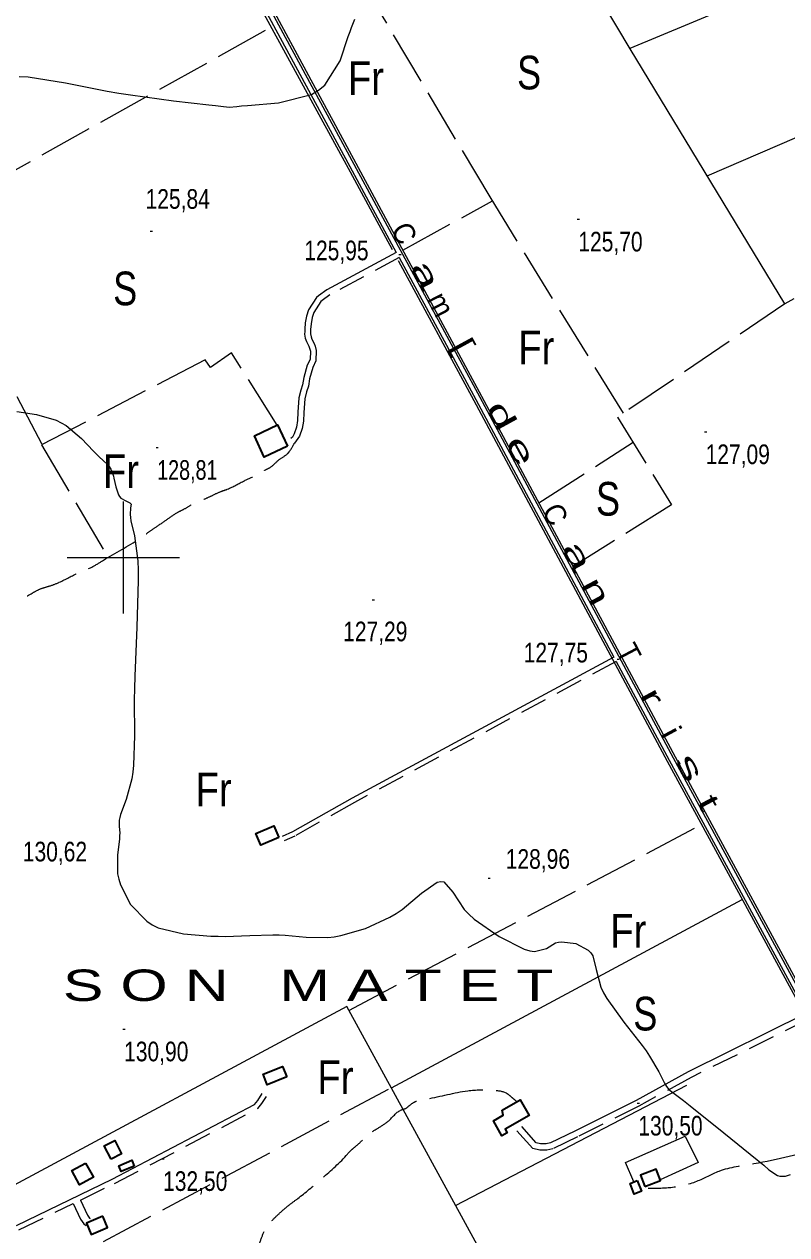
# Model space of a CAD drawing. Extents: x 487425 to 492029, y 4383576 to 4386788.
# Drawn here: x 488456 to 488796, y 4384698 to 4385238 of the extents above; entities that cross this region are included whole.
import ezdxf
from ezdxf.enums import TextEntityAlignment as Align

# ---------------------------------------------------------------- set-up
doc = ezdxf.new("R2010")
doc.units = 0
doc.header["$LTSCALE"] = 4
doc.linetypes.add('LONG_DASHED', pattern=[7.5, 6, -1.5])
doc.linetypes.add('MEDIUM_DASHED', pattern=[4.5, 3, -1.5])
for name, color, linetype, lineweight in [('1', 7, 'Continuous', 13), ('25', 7, 'LONG_DASHED', 25), ('38', 7, 'Continuous', 25), ('47', 7, 'Continuous', 35), ('51', 7, 'Continuous', 13), ('7', 7, 'Continuous', 13), ('8', 7, 'Continuous', 25), ('9', 7, 'Continuous', 13)]:
    doc.layers.add(name, color=color, linetype=linetype, lineweight=lineweight)
doc.layers.add('31', color=7, linetype='Continuous')
doc.layers.add('5', color=7, linetype='Continuous')

msp = doc.modelspace()

# ---------------------------------------------------------------- linework, layer by layer
at = {"layer": '1'}
for p, q in [((488500, 4385025), (488500, 4384975)), ((488475, 4385000), (488525, 4385000))]:
    msp.add_line(p, q, dxfattribs=at)
at = {"layer": '25'}
for p, q in [((488624.49, 4385136.87), (488664.45, 4385158.85)), ((488685.14, 4385024.33), (488727.05, 4385051.31)), ((488600.53, 4384798.28), (488757.61, 4384881.04)), ((488464.68, 4384681.15), (488619.38, 4384763.84))]:
    msp.add_line(p, q, dxfattribs=at)
for points in [[(488722.75, 4385064.26), (488663.36, 4385160.6), (488554.58, 4385343.42)], [(488463.94, 4385050.36), (488411.46, 4385150.11), (488566.15, 4385236.41)], [(488794.7, 4385112.97), (488720.16, 4385062.5), (488744.17, 4385023.44), (488700.34, 4384996)], [(488568.58, 4385058.95), (488548.16, 4385091.24), (488538.93, 4385084.59), (488536.42, 4385088), (488463.59, 4385050.19), (488492.89, 4385000.57)]]:
    msp.add_lwpolyline(points, dxfattribs=at)
at = {"layer": '38', "linetype": 'MEDIUM_DASHED'}
msp.add_line((488453.52, 4384700.52), (488477.75, 4384712.25), dxfattribs=at)
at = {"layer": '38'}
for points in [[(488512.49, 4385337.8), (488601.94, 4385172.22), (488621.59, 4385135.9)], [(488514.64, 4385338.17), (488603.76, 4385173.21), (488658.8, 4385071.45), (488744.97, 4384910.75), (488814.04, 4384783.4), (488837.88, 4384739.61)], [(488621.59, 4385135.9), (488590.67, 4385119.23), (488586.99, 4385116.53), (488586.05, 4385115.77), (488582.49, 4385110.29), (488581.66, 4385107.54), (488581.09, 4385104.47), (488580.83, 4385101.78), (488580.82, 4385100.7), (488580.8, 4385099.5), (488581.1, 4385097.73), (488581.58, 4385096.26), (488582.63, 4385094.19), (488583.03, 4385093.3), (488583.34, 4385091.89), (488583.23, 4385088.24), (488581.97, 4385085.64), (488580.45, 4385080.16), (488579.9, 4385076.96), (488579.05, 4385074.59), (488578.24, 4385071.12), (488577.78, 4385064.68), (488577.67, 4385060.96), (488577.2, 4385058.09), (488576.09, 4385055.13), (488575.33, 4385053.6), (488574.63, 4385053.04)], [(488622.83, 4385133.58), (488656.98, 4385070.46), (488718.58, 4384955.57)], [(488718.58, 4384955.57), (488601.92, 4384892.75), (488575.42, 4384877.82), (488570.83, 4384875.7)], [(488719.59, 4384953.71), (488743.15, 4384909.76), (488804.31, 4384796.99)], [(488804.31, 4384796.99), (488751.59, 4384770.9), (488728.41, 4384758.11), (488701.12, 4384744.55), (488690.36, 4384739.26), (488688.39, 4384738.87), (488685.81, 4384738.9), (488683.88, 4384739.3), (488677.49, 4384746.56)], [(488452.42, 4384702.52), (488495.02, 4384723.15), (488558.44, 4384756.33), (488559.88, 4384758.13), (488561.83, 4384761.19)], [(488480.92, 4384713.79), (488484.03, 4384707.09), (488484.93, 4384705.77), (488485.3, 4384705.55)]]:
    msp.add_lwpolyline(points, dxfattribs=at)
at = {"layer": '38', "linetype": 'MEDIUM_DASHED'}
for points in [[(488622.83, 4385133.58), (488592.08, 4385117.01), (488588.59, 4385114.45), (488588.02, 4385113.99), (488584.89, 4385109.18), (488584.22, 4385106.92), (488583.69, 4385104.1), (488583.46, 4385101.64), (488583.45, 4385100.66), (488583.43, 4385099.7), (488583.66, 4385098.36), (488584.01, 4385097.26), (488584.99, 4385095.32), (488585.53, 4385094.13), (488585.97, 4385092.14), (488585.83, 4385087.61), (488584.43, 4385084.71), (488583.01, 4385079.58), (488582.44, 4385076.29), (488581.57, 4385073.85), (488580.84, 4385070.73), (488580.4, 4385064.54), (488580.28, 4385060.71), (488579.75, 4385057.41), (488578.49, 4385054.08), (488576.26, 4385050.99)], [(488719.59, 4384953.71), (488602.94, 4384890.9), (488576.39, 4384875.94), (488571.71, 4384873.78)], [(488805.65, 4384794.52), (488752.89, 4384768.41), (488729.72, 4384755.62), (488702.37, 4384742.03), (488691.27, 4384736.57), (488688.65, 4384736.05), (488685.51, 4384736.09), (488682.39, 4384736.73), (488675.37, 4384744.7)], [(488480.92, 4384713.79), (488496.04, 4384721.12), (488559.91, 4384754.54), (488561.73, 4384756.8), (488563.75, 4384759.97)], [(488477.75, 4384712.25), (488480.95, 4384705.34), (488482.46, 4384703.14), (488483.49, 4384702.53)]]:
    msp.add_lwpolyline(points, dxfattribs=at)
at = {"layer": '38', "linetype": 'LONG_DASHED'}
for points in [[(488409.55, 4384948.7), (488422.25, 4384957.48), (488423.77, 4384958.74), (488425, 4384962.18), (488425.84, 4384963.37), (488427.82, 4384966.05), (488431.24, 4384969.31), (488434.11, 4384971.6), (488450.86, 4384979.74), (488459.46, 4384984.14), (488463.16, 4384986.05), (488467, 4384987.28), (488471.52, 4384988.96), (488480.05, 4384993.21), (488486.08, 4384995.77), (488491.14, 4384998.79), (488507.38, 4385008.51), (488511.01, 4385011.09), (488514.49, 4385013.53), (488519.48, 4385016.92), (488524.17, 4385020.09), (488527.19, 4385021.63), (488530.96, 4385023.84), (488535.33, 4385025.67), (488539.18, 4385027.42), (488543.48, 4385029.4), (488546.34, 4385030.42), (488554.04, 4385034.23), (488559.32, 4385036.72), (488562.26, 4385038.49), (488565.81, 4385040.4), (488569.45, 4385043.59), (488573.23, 4385046.32), (488574.37, 4385047.73), (488576.26, 4385050.99)], [(488487.92, 4384636.32), (488488.82, 4384636.16), (488492.56, 4384635.52), (488496.38, 4384634.65), (488502.07, 4384633.83), (488504.99, 4384633.65), (488507.47, 4384633.62), (488512.12, 4384633.72), (488516.25, 4384634.05), (488518.66, 4384634.62), (488536.11, 4384645.75), (488541.71, 4384650.11), (488544.29, 4384652.11), (488549, 4384657.83), (488549.39, 4384658.43), (488550.24, 4384660.67), (488552.51, 4384669.27), (488553.4, 4384674.66), (488555.19, 4384680.87), (488556.97, 4384685.2), (488559.74, 4384691.54), (488560.9, 4384694.91), (488562.99, 4384700.13), (488563.75, 4384701.4), (488565.58, 4384703.86), (488569.38, 4384707.71), (488573.77, 4384711.49), (488577.71, 4384714.45), (488587.86, 4384722.88), (488599.31, 4384733.63), (488601.74, 4384736.23), (488603.4, 4384737.63), (488606.21, 4384740.15), (488608.94, 4384742.75), (488613.85, 4384746.07), (488618.54, 4384749.39), (488623.92, 4384753.98), (488625.8, 4384754.64), (488627.54, 4384755.97), (488630.49, 4384757.81), (488635.3, 4384758.88), (488653.43, 4384762.5), (488664.76, 4384762.74), (488670.82, 4384761.33), (488673.2, 4384759.42), (488674.99, 4384757.95)], [(488833, 4384740.72), (488823.16, 4384739.41), (488817.75, 4384738.8), (488812.11, 4384737.36), (488780.89, 4384729.91), (488765.32, 4384726.57), (488755.29, 4384722.03), (488743.94, 4384719.31), (488733.73, 4384718.9)]]:
    msp.add_spline(points, degree=3, dxfattribs=at)
at = {"layer": '47'}
for points in [[(488573.19, 4385049.62), (488562.83, 4385044.73), (488558.39, 4385054.14), (488568.75, 4385059.03)], [(488569.26, 4384875.31), (488561.31, 4384871.89), (488559.08, 4384877.08), (488567.03, 4384880.5)], [(488572.85, 4384768.67), (488564.16, 4384765.17), (488562.28, 4384769.84), (488570.97, 4384773.34)], [(488668.71, 4384753.85), (488676.86, 4384758.48), (488680.81, 4384751.51), (488670.1, 4384745.44), (488671.07, 4384743.72), (488668.68, 4384742.37), (488664.85, 4384749.13), (488669.24, 4384751.62)], [(488494.56, 4384731.97), (488491.5, 4384737.91), (488496.23, 4384740.35), (488499.29, 4384734.41)], [(488483.21, 4384730.3), (488486.7, 4384723.96), (488480.55, 4384720.58), (488477.06, 4384726.92)], [(488504.88, 4384728.93), (488499.08, 4384726.48), (488497.98, 4384729.08), (488503.78, 4384731.53)], [(488732.31, 4384719.81), (488739.35, 4384722.44), (488737.43, 4384727.56), (488730.39, 4384724.93)], [(488728.97, 4384722.48), (488730.8, 4384717.74), (488727.55, 4384716.49), (488725.72, 4384721.23)], [(488490.89, 4384706.58), (488483.64, 4384703.52), (488485.77, 4384698.46), (488493.02, 4384701.52)]]:
    msp.add_lwpolyline(points, close=True, dxfattribs=at)
at = {"layer": '51'}
for p, q in [((488878.87, 4385290.5), (488725.63, 4385226.77)), ((488760.12, 4385169.94), (488965.78, 4385259.45)), ((488619.44, 4384763.73), (488775.73, 4384847.63)), ((488648.06, 4384711.42), (488750.98, 4384764.91))]:
    msp.add_line(p, q, dxfattribs=at)
for points in [[(488798.74, 4385115.18), (488794.7, 4385112.97), (488725.77, 4385226.51), (488646.35, 4385359.77)], [(488518.06, 4385334.28), (488604.59, 4385173.66), (488659.63, 4385071.9), (488745.8, 4384911.2), (488814.87, 4384783.85), (488835.8, 4384745.42)], [(488512.95, 4385333.39), (488601.07, 4385171.76), (488619.79, 4385137.16)], [(488622.46, 4385132.23), (488656.11, 4385070), (488742.28, 4384909.3), (488803.09, 4384797.19)], [(488570.54, 4384634.85), (488662.89, 4384684.29), (488599.61, 4384799.95), (488445.35, 4384717.23)], [(488727.38, 4384721.87), (488723.66, 4384730.57), (488750.27, 4384742.19), (488756.07, 4384730.57), (488739.21, 4384722.83)]]:
    msp.add_lwpolyline(points, dxfattribs=at)
at = {"layer": '7'}
for p, q in [((488702.2, 4385150.7), (488703.2, 4385150.7)), ((488512.04, 4385145.36), (488513.04, 4385145.36)), ((488622.73, 4385135.03), (488623.73, 4385135.03)), ((488758.89, 4385055.98), (488759.89, 4385055.98)), ((488514.62, 4385049), (488515.62, 4385049)), ((488610.85, 4384981.22), (488611.85, 4384981.22)), ((488719.93, 4384954.69), (488720.93, 4384954.69)), ((488662.48, 4384857.22), (488663.48, 4384857.22)), ((488499.89, 4384789.97), (488500.89, 4384789.97)), ((488728.93, 4384756.91), (488729.93, 4384756.91)), ((488517.24, 4384732.23), (488518.24, 4384732.23))]:
    msp.add_line(p, q, dxfattribs=at)
at = {"layer": '8'}
msp.add_lwpolyline([(488453.59, 4385214.26), (488457.63, 4385214.08), (488474.29, 4385211.5), (488492.79, 4385207.77), (488497.99, 4385206.87), (488503.23, 4385206.02), (488522.43, 4385203.46), (488538.05, 4385201.69), (488541.03, 4385201.36), (488543.42, 4385201.08), (488547.23, 4385200.66), (488547.23, 4385200.66), (488547.23, 4385200.66), (488547.23, 4385200.66), (488547.23, 4385200.66), (488547.23, 4385200.66), (488547.23, 4385200.66), (488547.23, 4385200.66), (488547.23, 4385200.66), (488550.59, 4385200.94), (488552.72, 4385201.12), (488555.35, 4385201.35), (488569.19, 4385202.53), (488583.86, 4385206.29), (488587.03, 4385208.14), (488589.81, 4385210.34), (488596.64, 4385221.21), (488600.25, 4385232.06), (488601, 4385234.25), (488601.64, 4385236.08), (488603.08, 4385239.76)], dxfattribs=at)
at = {"layer": '9'}
for points in [[(488452.64, 4385064.98), (488461.31, 4385063.74), (488470.17, 4385061.11), (488472.41, 4385060.03), (488474.54, 4385058.79), (488481.46, 4385053.01), (488486.81, 4385047.34), (488487.96, 4385046.16), (488488.96, 4385045.16), (488491.36, 4385042.96), (488492.72, 4385041.74), (488493.06, 4385041.36), (488493.39, 4385040.96), (488494.44, 4385039.33), (488495.38, 4385037.06), (488495.63, 4385036.25), (488495.88, 4385035.36), (488496.75, 4385031.49), (488497.93, 4385027.86), (488498.37, 4385027.12), (488498.87, 4385026.49), (488501.09, 4385025.18), (488502.98, 4385024.37), (488503.27, 4385024.06), (488503.46, 4385023.71), (488503.3, 4385022.12), (488503.07, 4385019.09), (488503.21, 4385017.83), (488503.44, 4385016.38), (488505, 4385009.62), (488506.48, 4384998.55), (488506.65, 4384994.39), (488506.72, 4384989.75), (488506.11, 4384969.03), (488505.15, 4384947.09), (488505, 4384941.68), (488504.9, 4384936.57), (488504.95, 4384920.52), (488504.61, 4384907.57), (488504.27, 4384904.42), (488503.82, 4384901.45), (488501.3, 4384892.28), (488498.85, 4384885.58), (488498.45, 4384884.17), (488498.16, 4384882.96), (488498.12, 4384880.18), (488498.45, 4384877.33), (488498.4, 4384876.06), (488498.29, 4384874.59), (488497.37, 4384867.56), (488497.47, 4384859.08), (488498, 4384856.68), (488498.75, 4384854.27), (488503.26, 4384845.42), (488510.49, 4384837.95), (488512.95, 4384836.41), (488515.61, 4384835.11), (488526.88, 4384832.31), (488539.06, 4384831.41), (488542.3, 4384831.3), (488545.47, 4384831.25), (488556.41, 4384831.58), (488566.68, 4384831.93), (488569.42, 4384831.89), (488572.13, 4384831.79), (488581.53, 4384830.94), (488591.14, 4384830.77), (488593.96, 4384831.11), (488596.86, 4384831.61), (488607.94, 4384834.79), (488618.79, 4384839.78), (488621.54, 4384841.42), (488624.19, 4384843.18), (488632.84, 4384850.44), (488639.82, 4384855.38), (488641.41, 4384855.67), (488642.85, 4384855.49), (488646.82, 4384850.92), (488651.8, 4384843.26), (488653.88, 4384841.12), (488656.26, 4384838.98), (488667.39, 4384831.2), (488678.6, 4384825.62), (488681.03, 4384824.87), (488683.17, 4384824.46)], [(488683.17, 4384824.46), (488688.47, 4384825.85), (488692.55, 4384828.39), (488693.92, 4384828.71), (488695.39, 4384828.86), (488701.57, 4384828.01), (488707.14, 4384825.07), (488708.23, 4384823.9), (488709.12, 4384822.58), (488710.7, 4384816.52), (488712.76, 4384808.62), (488713.96, 4384806.13), (488715.43, 4384803.51), (488723.01, 4384792.98), (488731.09, 4384782.67), (488732.87, 4384780.19), (488734.46, 4384777.88), (488738.57, 4384770.91), (488740.98, 4384766.12), (488741.49, 4384765.19), (488741.95, 4384764.42), (488743.05, 4384763.08), (488747.21, 4384759.98), (488749.6, 4384758.11), (488752.51, 4384755.79), (488767.5, 4384743.77), (488782.39, 4384731.65), (488785.25, 4384729.27), (488787.55, 4384727.32), (488791.39, 4384724.76), (488792.49, 4384724.44), (488795.03, 4384724.44), (488797.25, 4384725.24)]]:
    msp.add_lwpolyline(points, dxfattribs=at)

# ---------------------------------------------------------------- texts
at = {"layer": '31'}
for s, width, p in [('Fr', 0.85, (488608.07, 4385206.05)), ('S', 0.8, (488680.78, 4385208.52)), ('S', 0.8, (488500.86, 4385112.36)), ('Fr', 0.85, (488684, 4385086.01)), ('Fr', 0.85, (488499.02, 4385030.99)), ('S', 0.8, (488715.91, 4385018.66)), ('Fr', 0.85, (488540.29, 4384889.2)), ('Fr', 0.85, (488724.99, 4384826.18)), ('S', 0.8, (488732.53, 4384789.34)), ('Fr', 0.85, (488594.51, 4384760.99))]:
    msp.add_text(s, height=15, dxfattribs=dict(at, width=width)).set_placement(p, align=Align.CENTER)
at = {"layer": '5'}
for s, rotation, width, p in [('C', 297.241, 0.95, (488620.95, 4385142.28)), ('a', 297.241, 1.8, (488630.49, 4385123.75)), ('m', 297.241, 0.95, (488637.28, 4385110.58)), ('[', 298.715, 1.5, (488647.35, 4385092.24)), ('d', 298.715, 1.8, (488664.43, 4385061.04)), ('e', 298.715, 1.85, (488672.98, 4385045.46)), ('C', 298.259, 0.95, (488688.26, 4385017)), ('a', 298.259, 1.85, (488698.18, 4384998.54)), ('n', 297.8, 1.7, (488706.49, 4384982.83)), ('T', 297.8, 0.95, (488721.01, 4384955.32)), ('r', 298.154, 1.7, (488731.49, 4384935.67)), ('i', 298.154, 1.25, (488739.88, 4384919.99)), ('s', 298.154, 1.9, (488748.25, 4384904.34)), ('t', 298.154, 1.65, (488756.66, 4384888.63))]:
    msp.add_text(s, height=9.49, rotation=rotation, dxfattribs=dict(at, width=width)).set_placement(p, align=Align.CENTER)
at = {"layer": '5', "width": 1.45}
msp.add_text('S O N   M A T E T', height=13.99, dxfattribs=at).set_placement((488473.09, 4384802.48))
at = {"layer": '7'}
for s, width, p in [('125,84', 0.8, (488509.94, 4385155.34)), ('125,70', 0.8, (488702.7, 4385136.33)), ('125,95', 0.8, (488580.64, 4385132.4)), ('127,09', 0.8, (488759.39, 4385041.61)), ('128,81', 0.75, (488515.12, 4385034.63)), ('127,29', 0.8, (488597.95, 4384962.69)), ('127,75', 0.8, (488678.36, 4384953.27)), ('130,62', 0.8, (488455.27, 4384864.64)), ('128,96', 0.8, (488670.37, 4384861.35)), ('130,90', 0.8, (488500.39, 4384775.6)), ('130,50', 0.8, (488729.43, 4384742.54)), ('132,50', 0.8, (488517.74, 4384717.86))]:
    msp.add_text(s, height=8.75, dxfattribs=dict(at, width=width)).set_placement(p)

doc.saveas('drawing.dxf')
